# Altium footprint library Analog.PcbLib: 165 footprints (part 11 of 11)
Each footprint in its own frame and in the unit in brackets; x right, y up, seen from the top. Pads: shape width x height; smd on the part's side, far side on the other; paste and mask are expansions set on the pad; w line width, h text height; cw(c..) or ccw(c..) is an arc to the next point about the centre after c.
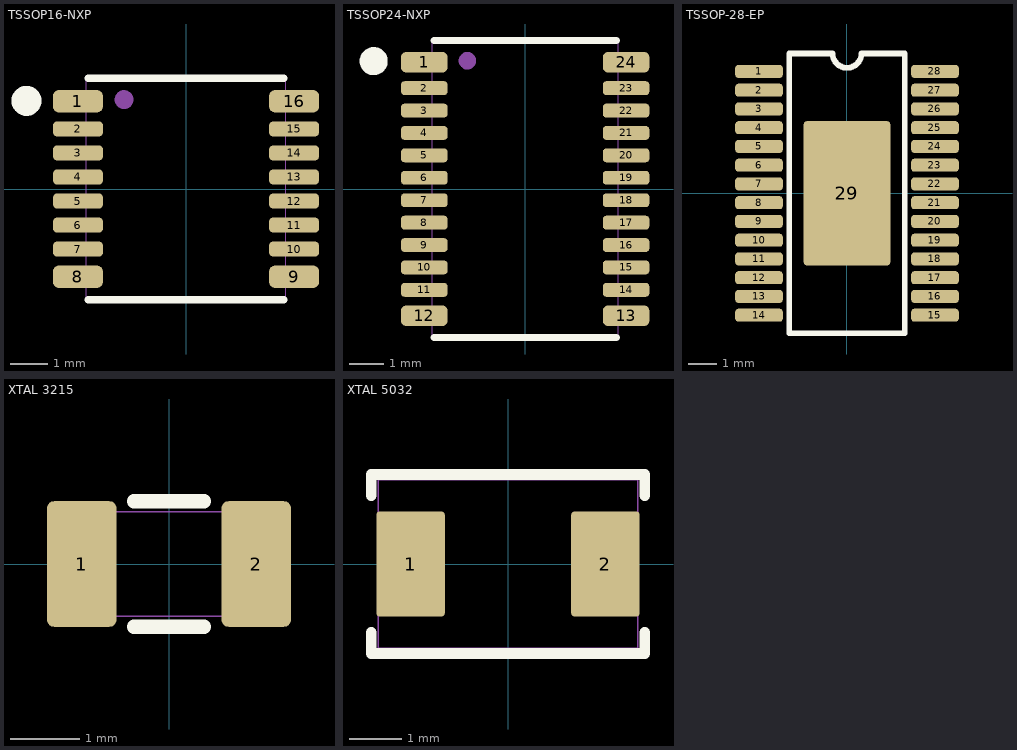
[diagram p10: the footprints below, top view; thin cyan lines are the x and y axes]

## TSSOP16-NXP [mm]
height 1.1
pads (16):
  rrect50% 1.35x0.6 smd paste+0 mask+0.05: 1(-2.925,2.375) 8(-2.925,-2.375) 9(2.925,-2.375) 16(2.925,2.375)
  rrect50% 1.35x0.4 smd paste+0 mask+0.05: 2(-2.925,1.625) 3(-2.925,0.975) 4(-2.925,0.325) 5(-2.925,-0.325) 6(-2.925,-0.975) 7(-2.925,-1.625) 10(2.925,-1.625) 11(2.925,-0.975) 12(2.925,-0.325) 13(2.925,0.325) 14(2.925,0.975) 15(2.925,1.625)
Top Overlay:
  circle w0.406: c-4.318,2.388 r0.203
  lines w0.203: -2.65,-3 2.65,-3 ; -2.65,3 2.65,3
Mechanical 13:
  circle w0.254: c-1.676,2.421 r0.127
  lines w0.025: -2.7,-3 2.7,-3 2.7,3 -2.7,3 -2.7,-3
  text ".Designator" at 0,2.7 h1.02

## TSSOP24-NXP [mm]
pads (24):
  rrect50% 1.35x0.6 smd paste+0 mask+0.05: 1(-2.925,3.675) 12(-2.925,-3.675) 13(2.925,-3.675) 24(2.925,3.675)
  rrect50% 1.35x0.4 smd paste+0 mask+0.05: 2(-2.925,2.925) 3(-2.925,2.275) 4(-2.925,1.625) 5(-2.925,0.975) 6(-2.925,0.325) 7(-2.925,-0.325) 8(-2.925,-0.975) 9(-2.925,-1.625) 10(-2.925,-2.275) 11(-2.925,-2.925) 14(2.925,-2.925) 15(2.925,-2.275) 16(2.925,-1.625) 17(2.925,-0.975) 18(2.925,-0.325) 19(2.925,0.325) 20(2.925,0.975) 21(2.925,1.625) 22(2.925,2.275) 23(2.925,2.925)
Top Overlay:
  circle w0.406: c-4.394,3.708 r0.203
  lines w0.203: -2.65,-4.3 2.65,-4.3 ; -2.65,4.3 2.65,4.3
Mechanical 13:
  circle w0.254: c-1.676,3.721 r0.127
  lines w0.025: -2.7,-4.3 -2.7,4.3 2.7,4.3 2.7,-4.3 -2.7,-4.3
  text ".Designator" at 0,4 h1.02

## TSSOP-28-EP [mm]
pads (29):
  rrect50% 1.65x0.45 smd mask+0.05: 1(-3.05,4.225) 2(-3.05,3.575) 3(-3.05,2.925) 4(-3.05,2.275) 5(-3.05,1.625) 6(-3.05,0.975) 7(-3.05,0.325) 8(-3.05,-0.325) 9(-3.05,-0.975) 10(-3.05,-1.625) 11(-3.05,-2.275) 12(-3.05,-2.925) 13(-3.05,-3.575) 14(-3.05,-4.225) 15(3.05,-4.225) 16(3.05,-3.575) 17(3.05,-2.925) 18(3.05,-2.275) 19(3.05,-1.625) 20(3.05,-0.975) 21(3.05,-0.325) 22(3.05,0.325) 23(3.05,0.975) 24(3.05,1.625) 25(3.05,2.275) 26(3.05,2.925) 27(3.05,3.575) 28(3.05,4.225)
  rrect7% 3x5 smd mask+0.05: 29(0,0)
Top Overlay:
  lines w0.2: -2,-4.85 -2,4.85 -0.5,4.85 ccw(c0,4.85) 0.5,4.85 2,4.85 2,-4.85 -2,-4.85

## XTAL 3215 [mm]
height 1.2
pads (2):
  rrect20% 1x1.8 smd: 1(-1.25,0) 2(1.25,0)
Top Overlay:
  lines w0.203: -0.5,-0.9 0.5,-0.9 ; -0.5,0.9 0.5,0.9
Mechanical 13:
  lines w0.025: -1.6,-0.75 -1.6,0.75 1.6,0.75 1.6,-0.75 -1.6,-0.75
  text ".Designator" at -2.261,-0.533 h1.02

## XTAL 5032 [mm]
height 1.2
pads (2):
  rrect10% 1.3x2 smd: 1(-1.85,0) 2(1.85,0)
Top Overlay:
  lines w0.203: -2.6,-1.3 -2.6,-1.7 2.6,-1.7 2.6,-1.3 ; -2.6,1.3 -2.6,1.7 2.6,1.7 2.6,1.3
Mechanical 13:
  lines w0.025: -2.464,-1.6 2.464,-1.6 2.464,1.6 -2.464,1.6 -2.464,-1.6
  text ".Designator" at -2.261,-0.533 h1.02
